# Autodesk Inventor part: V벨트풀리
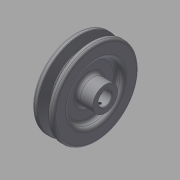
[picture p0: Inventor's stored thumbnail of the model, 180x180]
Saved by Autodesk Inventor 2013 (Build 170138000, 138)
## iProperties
Created: 2015-11
Part Number: V벨트풀리
Material: 강철, 탄소
Document SubType Name: Modeling
Designer: mduedu
Density: 7.87 g/cm^3
Mass: 425.958 g
Surface Area: 184.412 cm^2
Volume: 54.1243 cm^3
Author: mduedu
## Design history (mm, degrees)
sketch "스케치1"
  geometry: L1 (-9.5, 0)-(9.5, 0); L2 (0, 0)-(0, 37.7); L3 (-4.825, 37.7)-(-9.5, 37.7); L4 (-9.5, 37.7)-(-9.5, 0); L5 (0, 28.7)-(-2.074, 28.7); L6 (-2.074, 28.7)-(-4.825, 37.7); L7 (4.825, 37.7)-(9.5, 37.7); L8 (9.5, 37.7)-(9.5, 0); L9 (0, 28.7)-(2.074, 28.7); L10 (2.074, 28.7)-(4.825, 37.7); L11 (-9.5, 35)-(9.5, 35); 3 further points
  constraints: 22 end point, 7 point on line, 4 perpendicular, 3 symmetric about line, 1 coincident, 1 horizontal, 1 horizontal alignment, 1 midpoint, 1 vertical
  dimensions: "d0" = 19 distance of L1.start L1.end; "d2" = 75.4 diameter of L2.end L1 (derived); "d3" = 34 deg angle of L10 L6; "d4" = 6.3 distance between parallel lines of L11 L9; "d5" = 2.7 distance between parallel lines of L7 L11; "d6" = 8 distance of point (4, 35) point (-4, 35); "d7" = 70 diameter of L11 L1
revolve "회전1" sketch "스케치1" stored, may be unused: angle "d8" = 90 deg
sketch "스케치2"
  geometry: C1 r 24 at (0, 0); C2 r 11 at (0, 0); 1 further point
  constraints: 2 centre point, 2 coincident
  dimensions: "d9" = 48 diameter of C1; "d10" = 22 diameter of C2
extrude "돌출1" cut sketch "스케치2" distance "d11" = 6; taper "d12" = 0 deg
extrude "돌출3" join sketch "스케치2" distance "d37" = 8; taper "d38" = 0 deg
fillet "모깎기1" dims "d13" = 3
fillet "모깎기2" dims "d14" = 3
fillet "모깎기3" dims "d15" = 1, "d16" = 0.5, "d17" = 2
hole "구멍1" diameter "d20" = 12; stored, may be unused: countersink angle "d24" = 90 deg, drill point angle "d26" = 118 deg; dims "d21" = 6, "d22" = 4, "d23" = 2, "d25" = 8, "d58" = 10, "d59" = 10
sketch "스케치3"
  geometry: L1 (-2, 0)-(2, 0); L2 (2, 0)-(2, 7.8); L3 (2, 7.8)-(-2, 7.8); L4 (-2, 7.8)-(-2, 0); 2 further points
  constraints: 8 end point, 2 parallel, 1 coincident, 1 horizontal, 1 midpoint, 1 perpendicular
  dimensions: "d27" = 4 distance of L2.end L3.end; "d29" = 7.8 distance of L3.end L1.start
extrude "돌출2" cut sketch "스케치3" stored distance "d30" = 6; taper "d31" = 0 deg
node "작업 평면1"
sketch "스케치4"
  geometry: L1 (19, -27)-(19, 27) reference; 2 further points
  constraints: 1 horizontal alignment
  dimensions: "d52" = 22 distance from line of L1 point (-3, 0)
hole "구멍2" sketch "스케치4" at (-3, 0) diameter "d42" = 2.459; stored, may be unused: countersink angle "d46" = 90 deg, drill point angle "d48" = 118 deg; dims "d43" = 6, "d44" = 4, "d45" = 2, "d47" = 8
chamfer "모따기3" distance "d60" = 0.5; stored, may be unused: second distance "d61" = 2, angle "d62" = 45 deg
node "솔리드1"
mirror "대칭1"
